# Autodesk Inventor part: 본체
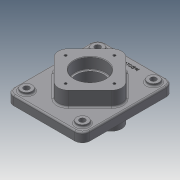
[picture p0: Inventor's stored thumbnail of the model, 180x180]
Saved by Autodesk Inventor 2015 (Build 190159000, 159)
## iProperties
Created: 2026-07
Part Number: 본체
Material: 일반
Document SubType Name: Modeling
Designer: user
Density: 1 g/cm^3
Appearance: 기본값
Author: user
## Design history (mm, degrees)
sketch "스케치1"
  geometry: L1 (-75, 90)-(75, 90); L2 (75, 90)-(75, -90); L3 (75, -90)-(-75, -90); L4 (-75, -90)-(-75, 90); L5 (-75, 90)-(75, -90); L6 (75, 90)-(-75, -90); 1 further point
  constraints: 12 end point, 2 midpoint, 2 parallel, 1 horizontal, 1 perpendicular
  dimensions: "d0" = 150 distance of L2.end L3.end; "d1" = 180 distance of L1.end L2.end
extrude "돌출1" new body sketch "스케치1" distance "d2" = 18; taper "d3" = 0 deg
fillet "모깎기1" dims "d4" = 15
sketch "스케치2"
  geometry: L1 (0, -70.711)-(-70.711, 0); L2 (-70.711, 0)-(0, 70.711); L3 (0, 70.711)-(70.711, 0); L4 (70.711, 0)-(0, -70.711); 2 further points
  constraints: 8 end point, 1 coincident, 1 vertical alignment, 9 other
  dimensions: "d5" = 100 distance of L2.end L3.end
extrude "돌출2" join sketch "스케치2" distance "d6" = 29; taper "d7" = 0 deg; dims "d17" = 41, "d18" = 0
fillet "모깎기2" dims "d8" = 20
fillet "모깎기3" dims "d19" = 20
sketch "스케치3"
  geometry: L1 (0, 0)-(0, 48)
  constraints: 2 end point, 1 vertical
  dimensions: "d9" = 48 distance of L1.start L1.end
hole "구멍1" sketch "스케치3" at (0, 48) diameter "d10" = 4.917; stored, may be unused: countersink angle "d14" = 90 deg, drill point angle "d16" = 118 deg; dims "d11" = 10, "d12" = 4, "d13" = 2, "d15" = 13
hole "구멍2" diameter "d22" = 54; stored, may be unused: countersink angle "d26" = 90 deg, drill point angle "d28" = 0 deg; dims "d20" = 50, "d21" = 50, "d23" = 10, "d24" = 62, "d25" = 22, "d27" = 13
hole "구멍3" diameter "d31" = 62; stored, may be unused: countersink angle "d35" = 90 deg, drill point angle "d37" = 0 deg; dims "d29" = 10, "d30" = 10, "d32" = 10, "d33" = 62, "d34" = 22, "d36" = 22
sketch "스케치5"
  geometry: L1 (-75, -75)-(-75, 75) reference; L2 (-60, 90)-(60, 90) reference; C1 r 11 at (-55, 70); 1 further point
  constraints: 1 centre point
  dimensions: "d41" = 22 diameter of C1; "d42" = 20 distance from line of L1 C1.centre; "d43" = 20 distance from line of C1.centre L2
extrude "돌출3" join sketch "스케치5" distance "d44" = 5; taper "d45" = 0 deg
hole "구멍4" diameter "d48" = 11; stored, may be unused: countersink angle "d52" = 90 deg, drill point angle "d54" = 0 deg; dims "d46" = 10, "d47" = 10, "d49" = 10, "d50" = 62, "d51" = 22, "d53" = 22
sketch "스케치6"
  geometry: L1 (-60, 90)-(60, 90) reference; 2 further points
  constraints: 1 vertical alignment, 1 other
  dimensions: "d61" = 15 distance from line of point (0, 75) L1
feature "엠보싱1" sketch "스케치6" dims "d0" = 150, "d1" = 180, "d62" = 0.5, "d63" = 0
sketch "스케치7"
  geometry: L1 (0, 0)-(0, 48)
  constraints: 2 end point, 1 vertical
  dimensions: "d64" = 48 distance of L1.start L1.end
hole "구멍5" sketch "스케치7" at (0, 48) diameter "d65" = 4.917; stored, may be unused: countersink angle "d69" = 90 deg, drill point angle "d71" = 118 deg; dims "d66" = 10, "d67" = 4, "d68" = 2, "d70" = 13
fillet "모깎기4" dims "d75" = 1
chamfer "모따기1" distance "d76" = 1; stored, may be unused: second distance "d77" = 2, angle "d78" = 45 deg
fillet "모깎기5" dims "d79" = 3
node "솔리드1"
pattern_circular "원형 패턴1" dims angle "d39" = 360 deg
pattern_linear "직사각형 패턴1"
pattern_circular "원형 패턴2" dims angle "d73" = 360 deg
